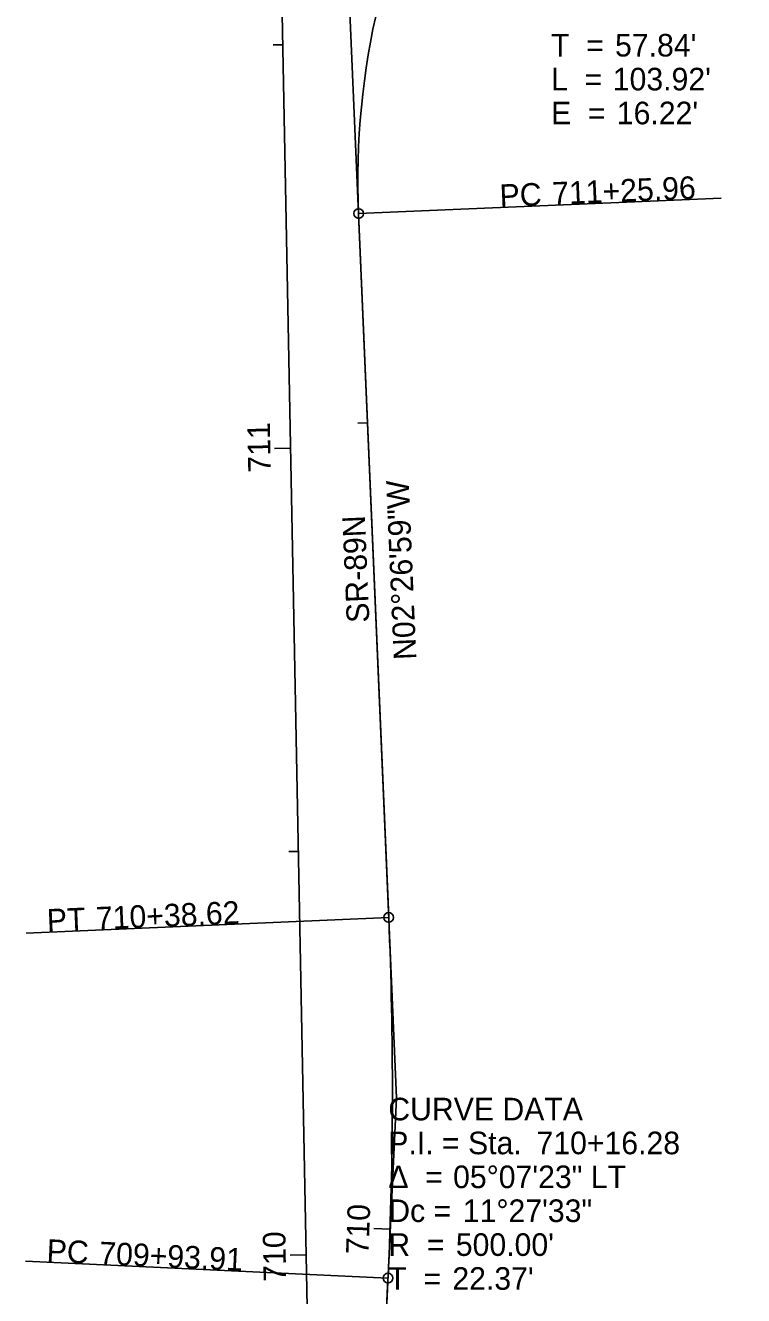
# Model space of a CAD drawing. Extents: x 2047151 to 2048731, y 456453 to 457874.
# Drawn here: x 2047602.8 to 2047691.9, y 456751.4 to 456908.9 of the extents above; entities that cross this region are included whole.
import ezdxf

# ---------------------------------------------------------------- set-up
doc = ezdxf.new("R2010")
doc.units = 0
for name, color, linetype in [('GE_P_Alignment', 7, 'Continuous'), ('GE_P_Alignment_100_Stations', 7, 'Continuous'), ('GE_P_Alignment_500_Bearings', 7, 'Continuous'), ('GE_P_Alignment_500_Cardinal_Points', 7, 'Continuous'), ('GE_P_Alignment_500_Curve_Data', 7, 'Continuous'), ('GE_P_Alignment_500_Distances', 7, 'Continuous'), ('GE_P_Alignment_500_Stations', 7, 'Continuous')]:
    doc.layers.add(name, color=color, linetype=linetype)

msp = doc.modelspace()

# ---------------------------------------------------------------- linework, layer by layer
at = {"layer": 'GE_P_Alignment'}
for p, q in [((2047643.48, 456456.55), (2047633.52, 456968.93)), ((2047648.82, 456775.95), (2047641.42, 456948.9)), ((2047643.48, 456456.55), (2047634.45, 456921.29)), ((2047647.87, 456798.3), (2047644.14, 456885.55)), ((2047637.42, 456531.68), (2047648.82, 456775.95)), ((2047643.61, 456664.31), (2047647.78, 456753.6))]:
    msp.add_line(p, q, dxfattribs=at)
for centre, radius, start, end in [((2047739.05, 456889.61), 95, 119.7772, 182.4498), ((2047739.05, 456889.61), 95, 119.7772, 182.4498), ((2047148.33, 456776.92), 500, 357.3267, 2.4498), ((2047148.33, 456776.92), 500, 357.3267, 2.4498)]:
    msp.add_arc(centre, radius, start, end, dxfattribs=at)
at = {"layer": 'GE_P_Alignment_100_Stations'}
for p, q in [((2047634.73, 456906.47), (2047633.53, 456906.45)), ((2047635.71, 456856.48), (2047633.71, 456856.44)), ((2047636.68, 456806.49), (2047635.48, 456806.46)), ((2047637.65, 456756.5), (2047635.65, 456756.46))]:
    msp.add_line(p, q, dxfattribs=at)
at = {"layer": 'GE_P_Alignment_500_Cardinal_Points'}
for p, q in [((2047644.14, 456885.55), (2047689.09, 456887.47)), ((2047647.87, 456798.3), (2047602.91, 456796.37)), ((2047647.78, 456753.6), (2047602.83, 456755.7))]:
    msp.add_line(p, q, dxfattribs=at)
for centre in [(2047644.14, 456885.55), (2047647.87, 456798.3), (2047647.78, 456753.6)]:
    msp.add_circle(centre, 0.6, dxfattribs=at)
at = {"layer": 'GE_P_Alignment_500_Stations'}
for p, q in [((2047645.24, 456859.62), (2047644.05, 456859.57)), ((2047648.03, 456759.68), (2047646.03, 456759.75))]:
    msp.add_line(p, q, dxfattribs=at)

# ---------------------------------------------------------------- texts
at = {"layer": 'GE_P_Alignment_100_Stations'}
for s, p in [('711', (2047633.26, 456853.46)), ('710', (2047635.17, 456753.17))]:
    msp.add_text(s, height=2.8, rotation=91.1135, dxfattribs=at).set_placement(p)
at = {"layer": 'GE_P_Alignment_500_Bearings'}
msp.add_text('N02°26\'59"W', height=2.8, rotation=92.4498, dxfattribs=at).set_placement((2047651.3, 456830.28))
at = {"layer": 'GE_P_Alignment_500_Cardinal_Points'}
for s, rotation, p in [('711+25.96', 2.4498, (2047668.2, 456886.63)), ('PC', 2.4498, (2047661.68, 456886.35)), ('710+38.62', 2.4498, (2047611.63, 456796.79)), ('PT', 2.4498, (2047605.55, 456796.53)), ('PC', 357.3267, (2047605.42, 456755.63)), ('709+93.91', 357.3267, (2047611.94, 456755.32))]:
    msp.add_text(s, height=2.8, rotation=rotation, dxfattribs=at).set_placement(p)
at = {"layer": 'GE_P_Alignment_500_Curve_Data'}
for s, p in [('T  = ', (2047668, 456905.01)), ("57.84'", (2047675.93, 456905.01)), ('L  = ', (2047668, 456900.81)), ("103.92'", (2047675.65, 456900.81)), ("16.22'", (2047676.15, 456896.61)), ('E  = ', (2047668, 456896.61)), ('CURVE DATA', (2047647.82, 456773.15)), ('P.I. = Sta. ', (2047647.82, 456768.95)), ('710+16.28', (2047666.19, 456768.95)), ('Δ  = ', (2047647.82, 456764.75)), ('05°07\'23" LT', (2047655.85, 456764.75)), ('Dc = ', (2047647.82, 456760.55)), ('11°27\'33"', (2047657.06, 456760.55)), ('R  = ', (2047647.82, 456756.35)), ("500.00'", (2047656.19, 456756.35)), ('T  = ', (2047647.82, 456752.15)), ("22.37'", (2047655.76, 456752.15))]:
    msp.add_text(s, height=2.8, dxfattribs=at).set_placement(p)
at = {"layer": 'GE_P_Alignment_500_Distances'}
msp.add_text('SR-89N', height=2.8, rotation=92.4498, dxfattribs=at).set_placement((2047645.48, 456834.88))
at = {"layer": 'GE_P_Alignment_500_Stations'}
msp.add_text('710', height=2.8, rotation=88.024, dxfattribs=at).set_placement((2047645.37, 456756.49))

doc.saveas('drawing.dxf')
